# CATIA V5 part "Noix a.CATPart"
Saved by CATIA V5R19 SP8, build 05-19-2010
Part number: Noix a
Bounding box of the stored display mesh (mm): x 0 to 100, y -28 to 0, z 0 to 5
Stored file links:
  F:\CFAO\Hberriche\Noix a.CATPart
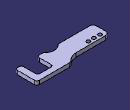
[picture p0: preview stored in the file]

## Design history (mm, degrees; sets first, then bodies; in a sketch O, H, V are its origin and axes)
Parameters
  `Largeur noix` = 28 mm
  `Ecart noix` = 20 mm
  `Profondeur noix` = 21 mm
Body1 (main body)
  Sketch1 on xy-plane, origin (0, 0, 0), H (1, 0, 0), V (0, 1, 0)
    line L1 (0, -12) -> (0, -23)
    point P1 (0, -7)
    point P2 (0, -28)
    line L2 (5, -28) -> (45, -28)
    point P3 (45, -28)
    line L3 (5, -7) -> (43.101, -7)
    point P4 (50, -7)
    line L4 (54.4898, -1.7619) -> (54.5034, -1.746)
    point P5 (56, 0)
    line L5 (58.2997, 0) -> (97, 0)
    point P6 (100, 0)
    line L6 (100, -3) -> (100, -25)
    point P7 (100, -28)
    line L7 (97, -28) -> (95, -28)
    point P8 (92, -28)
    line L8 (92, -25) -> (92, -10)
    point P9 (92, -7)
    line L9 (89, -7) -> (75, -7)
    point P10 (72, -7)
    line L10 (72, -10) -> (72, -25)
    point P11 (72, -28)
    line L11 (69, -28) -> (64, -28)
    point P12 (64, -28)
    arc A1 centre (54.5, -35.3314) radius 12 from (45, -28) to (64, -28) cw
    arc A2 centre (5, -12) radius 5 from (5, -7) to (0, -12) ccw
    arc A3 centre (5, -23) radius 5 from (0, -23) to (5, -28) ccw
    arc A4 centre (69, -25) radius 3 from (69, -28) to (72, -25) ccw
    arc A5 centre (75, -10) radius 3 from (72, -10) to (75, -7) cw
    arc A6 centre (89, -10) radius 3 from (89, -7) to (92, -10) cw
    arc A7 centre (95, -25) radius 3 from (92, -25) to (95, -28) ccw
    arc A8 centre (97, -25) radius 3 from (97, -28) to (100, -25) ccw
    arc A9 centre (97, -3) radius 3 from (97, 0) to (100, -3) cw
    arc A10 centre (58.2997, -5) radius 5 from (54.5034, -1.746) to (58.2997, 0) cw
    arc A11 centre (43.101, 8) radius 15 from (43.101, -7) to (54.4898, -1.7619) ccw
    distance L1 L6 = 100
    distance P12 P3 = 19
    radius A1 = 12
    distance P1 P4 = 50
    radius A2 = 5
    distance P2 P3 = 45
    radius A3 = 5
    radius A4 = 3
    distance P9 P10 = 20 {= `Ecart noix`}
    radius A5 = 3
    distance P8 P9 = 21 {= `Profondeur noix`}
    radius A6 = 3
    distance P7 P8 = 8
    radius A7 = 3
    distance P6 P7 = 28 {= `Largeur noix`}
    radius A8 = 3
    distance P5 P6 = 44
    radius A9 = 3
    radius A10 = 5
    radius A11 = 15
    coincidence: P1 V, P5 H, P7 L2, P9 L3, P11 L2, L3 P1, L1 P1, L1 P2, L2 P2, L11 P11, L10 P11, L10 P10, L9 P10, L9 P9, L8 P9, L8 P8, L7 P8, L7 P7, L6 P7, L5 P6, L6 P6, L4 P5, L5 P5, L3 P4, L4 P4
    vertical: L1 V, L6 V, L8 V, L10 V
    horizontal: L2 H, L3 H, L5 H, L7 H, L9 H, L11 H
    tangency: A2 L3, A2 L1, A3 L1, A3 L2, A4 L11, A4 L10, A5 L10, A5 L9, A6 L9, A6 L8, A7 L8, A7 L7, A8 L7, A8 L6, A9 L5, A9 L6, A10 L4, A10 L5, A11 L3, A11 L4
  Pad1: profile Sketch1, direction (0, 0, 1), length 5
  DatumCurve1
  Sketch2 on end face of Pad1, origin (0, 0, 5), H (1, 0, 0), V (0, 1, 0)
    circle A1 centre (15, -11.7928) radius 2.5
    reference projected circle E1 centre (15, -11.7928) radius 2.5 from edge of DatumCurve1
    radius A1 = 2.5
    concentricity: E1 A1
  Pocket1: profile Sketch2, direction (0, 0, -1), through (limit type 3)
  DatumCurve2 to DatumCurve7
  Sketch3 on start face of Pad1, origin (0, 0, 0), H (1, 0, 0), V (0, -1, 0)
    circle A1 centre (22.5, 11.5833) radius 2.5
    circle A2 centre (7.5, 11.5833) radius 2.5
    reference projected circle E1 centre (7.5, 11.5833) radius 2.5 from edge of DatumCurve6
    reference projected circle E2 centre (22.5, 11.5833) radius 2.5 from edge of DatumCurve7
    radius A1 = 2.5
    radius A2 = 2.5
    concentricity: E1 A2, E2 A1
  Pocket2: profile Sketch3, direction (0, 0, 1), through (limit type 3)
